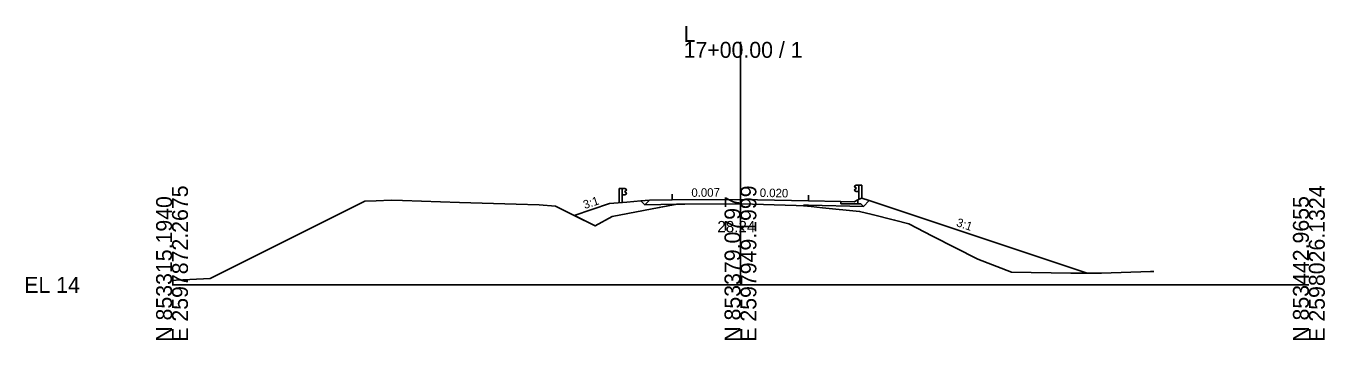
# Model space of a CAD drawing. Extents: x -26 to 1203, y -10 to 9526.
# Drawn here: x -25.7 to 202.8, y 6990.3 to 7045.5 of the extents above; entities that cross this region are included whole.
import ezdxf

# ---------------------------------------------------------------- set-up
doc = ezdxf.new("R2010")
doc.units = 0
for name, color, linetype in [('Exist Cross Section Cell', 7, 'Continuous'), ('Exist XS Center Line Elevation Label', 7, 'Continuous'), ('Exist XS Ground Line', 7, 'Continuous'), ('Prop XS Earthwork Shape', 7, 'Continuous'), ('Prop XS EOT Tick Mark', 7, 'Continuous'), ('Prop XS Finish Grade', 7, 'Continuous'), ('Prop XS Finish Grade Earthwork', 7, 'Continuous'), ('Prop XS Finish Grade Paved Shoulder', 7, 'Continuous'), ('Prop XS Finish Grade Pavement', 7, 'Continuous'), ('Prop XS Guardrail', 7, 'Continuous'), ('Prop XS Pvmt Edge Slope', 7, 'Continuous'), ('Prop XS SBG', 7, 'Continuous'), ('Prop XS SE Text', 7, 'Continuous'), ('Prop XS Side Slope Text', 7, 'Continuous'), ('Prop XS Subgrade Earthwork', 7, 'Continuous')]:
    doc.layers.add(name, color=color, linetype=linetype)

msp = doc.modelspace()

# ---------------------------------------------------------------- linework, layer by layer
at = {"layer": 'Exist Cross Section Cell'}
for p, q in [((100, 7000), (100, 7042.73)), ((0, 7000), (100, 7000)), ((100, 7000), (200, 7000))]:
    msp.add_line(p, q, dxfattribs=at)
at = {"layer": 'Exist XS Ground Line'}
for p, q in [((6.7, 7001.12), (32.07, 7013.81)), ((32.07, 7013.81), (33.91, 7014.73)), ((33.91, 7014.73), (35.91, 7014.79)), ((35.91, 7014.79), (38.54, 7014.87)), ((38.54, 7014.87), (40.54, 7014.81)), ((40.54, 7014.81), (50.55, 7014.51)), ((50.55, 7014.51), (60.56, 7014.21)), ((60.56, 7014.21), (64.57, 7014.09)), ((64.57, 7014.09), (67.48, 7013.86)), ((67.48, 7013.86), (74.43, 7010.38)), ((85.71, 7013.58), (88.86, 7014.2)), ((88.86, 7014.2), (90.2, 7014.21)), ((90.2, 7014.21), (100.2, 7014.24)), ((100.2, 7014.24), (109.81, 7013.95)), ((109.81, 7013.95), (111.12, 7013.93)), ((111.12, 7013.93), (112.45, 7013.77)), ((112.45, 7013.77), (114.46, 7013.56)), ((74.43, 7010.38), (77.41, 7012.04)), ((77.41, 7012.04), (85.71, 7013.58)), ((114.46, 7013.56), (120.95, 7012.91)), ((120.95, 7012.91), (123.15, 7012.36)), ((123.15, 7012.36), (127.11, 7011.4)), ((127.11, 7011.4), (129.61, 7010.71)), ((129.61, 7010.71), (133.78, 7008.54)), ((133.78, 7008.54), (141.75, 7004.52)), ((141.75, 7004.52), (147.66, 7002.22)), ((163.52, 7002.04), (172.11, 7002.36)), ((172.11, 7002.36), (172.71, 7002.38)), ((0, 7000.77), (0.74, 7000.81)), ((0.74, 7000.81), (6.7, 7001.12)), ((147.66, 7002.22), (158.11, 7002.04)), ((158.11, 7002.04), (163.52, 7002.04))]:
    msp.add_line(p, q, dxfattribs=at)
at = {"layer": 'Prop XS Earthwork Shape'}
for points in [[(88.74, 7014.18), (83.19, 7014.07), (82.5, 7014.76), (80, 7014.56), (76.99, 7014.32), (70.73, 7012.23), (74.43, 7010.38), (77.41, 7012.04), (85.71, 7013.58)], [(88.86, 7014.2), (88.86, 7014.18), (88.74, 7014.18)], [(111.12, 7014.02), (111.12, 7013.93), (112.45, 7013.77), (114.46, 7013.56), (120.95, 7012.91), (123.15, 7012.36), (127.11, 7011.4), (129.61, 7010.71), (133.78, 7008.54), (141.75, 7004.52), (147.66, 7002.22), (158.11, 7002.04), (161.01, 7002.04), (122.64, 7014.83), (121.62, 7013.81), (112, 7014)]]:
    msp.add_lwpolyline(points, close=True, dxfattribs=at)
at = {"layer": 'Prop XS EOT Tick Mark'}
for p, q in [((88, 7014.96), (88, 7015.96)), ((112, 7014.79), (112, 7015.79))]:
    msp.add_line(p, q, dxfattribs=at)
at = {"layer": 'Prop XS Finish Grade'}
for p, q in [((84, 7014.88), (82.5, 7014.76)), ((120.67, 7014.93), (121.31, 7015.25)), ((121.33, 7015.26), (122.64, 7014.83))]:
    msp.add_line(p, q, dxfattribs=at)
at = {"layer": 'Prop XS Finish Grade Earthwork'}
for p, q in [((76.99, 7014.32), (70.73, 7012.23)), ((80, 7014.56), (76.99, 7014.32)), ((82.5, 7014.76), (80, 7014.56)), ((122.64, 7014.83), (161.01, 7002.04))]:
    msp.add_line(p, q, dxfattribs=at)
at = {"layer": 'Prop XS Finish Grade Paved Shoulder'}
for p, q in [((88, 7014.96), (84, 7014.88)), ((112, 7014.79), (117.67, 7014.68))]:
    msp.add_line(p, q, dxfattribs=at)
at = {"layer": 'Prop XS Finish Grade Pavement'}
for p, q in [((88, 7014.96), (100, 7015.03)), ((100, 7015.03), (112, 7014.79))]:
    msp.add_line(p, q, dxfattribs=at)
at = {"layer": 'Prop XS Guardrail'}
for p, q in [((78.67, 7016.95), (79.17, 7016.95)), ((78.67, 7014.45), (78.67, 7016.95)), ((79.17, 7016.95), (79.67, 7016.95)), ((79.17, 7016.95), (79.17, 7014.45)), ((79.67, 7016.95), (79.96, 7016.75)), ((79.96, 7016.63), (79.67, 7016.43)), ((79.67, 7016.43), (79.67, 7016.34)), ((79.67, 7016.34), (79.96, 7016.14)), ((79.96, 7016.02), (79.67, 7015.82)), ((79.96, 7016.75), (79.99, 7016.69)), ((79.99, 7016.69), (79.96, 7016.63)), ((79.96, 7016.14), (79.99, 7016.08)), ((79.99, 7016.08), (79.96, 7016.02)), ((120.04, 7017.36), (120.01, 7017.3)), ((120.01, 7017.3), (120.04, 7017.24)), ((120.04, 7016.74), (120.01, 7016.68)), ((120.01, 7016.68), (120.04, 7016.62)), ((120.33, 7017.56), (120.04, 7017.36)), ((120.04, 7017.24), (120.33, 7017.04)), ((120.33, 7016.94), (120.04, 7016.74)), ((120.04, 7016.62), (120.33, 7016.42)), ((120.83, 7017.56), (120.33, 7017.56)), ((120.33, 7017.04), (120.33, 7016.94)), ((120.33, 7016.42), (120.83, 7016.42)), ((121.33, 7017.56), (120.83, 7017.56)), ((120.83, 7017.56), (120.83, 7015.01)), ((121.33, 7015.26), (121.33, 7017.56)), ((79.67, 7015.82), (79.17, 7015.82))]:
    msp.add_line(p, q, dxfattribs=at)
at = {"layer": 'Prop XS Pvmt Edge Slope'}
for p, q in [((84, 7014.88), (83.19, 7014.07)), ((120.67, 7014.26), (121.17, 7014.26)), ((121.17, 7014.26), (121.62, 7013.81))]:
    msp.add_line(p, q, dxfattribs=at)
at = {"layer": 'Prop XS SBG'}
for p, q in [((117.67, 7014.68), (117.67, 7014.26)), ((120, 7014.6), (117.67, 7014.68)), ((117.67, 7014.26), (120.67, 7014.26)), ((120.67, 7014.93), (120, 7014.6)), ((120.67, 7014.26), (120.67, 7014.93))]:
    msp.add_line(p, q, dxfattribs=at)
at = {"layer": 'Prop XS Subgrade Earthwork'}
for p, q in [((83.19, 7014.07), (82.5, 7014.76)), ((88.86, 7014.18), (83.19, 7014.07)), ((88.86, 7014.2), (88.86, 7014.18)), ((111.12, 7014.02), (111.12, 7013.93)), ((111.12, 7014.02), (112, 7014)), ((112, 7014), (121.62, 7013.81)), ((121.62, 7013.81), (122.64, 7014.83))]:
    msp.add_line(p, q, dxfattribs=at)

# ---------------------------------------------------------------- texts
at = {"layer": 'Exist Cross Section Cell'}
for s, p in [('L', (90, 7042.73)), ('17+00.00 / 1', (90, 7039.93)), ('EL 14', (-26, 6998.6))]:
    msp.add_text(s, height=2.8, dxfattribs=at).set_placement(p)
for s, p in [('E 2597872.2675', (2.8, 6990)), ('E 2597949.1999', (102.8, 6990)), ('E 2598026.1324', (202.8, 6990)), ('N 853315.1940', (0, 6990)), ('N 853379.0797', (100, 6990)), ('N 853442.9655', (200, 6990))]:
    msp.add_text(s, height=2.8, rotation=90, dxfattribs=at).set_placement(p)
at = {"layer": 'Exist XS Center Line Elevation Label'}
msp.add_text('28.24', height=2, dxfattribs=at).set_placement((95.93, 7009.24))
at = {"layer": 'Prop XS SE Text'}
for s, rotation, p in [('0.007', 0.3745, (91.37, 7015.48)), ('0.020', 358.8542, (103.38, 7015.47))]:
    msp.add_text(s, height=1.5, rotation=rotation, dxfattribs=at).set_placement(p)
at = {"layer": 'Prop XS Side Slope Text'}
for rotation, p in [(18.4349, (72.61, 7013.32)), (341.5651, (137.86, 7010.36))]:
    msp.add_text('3:1', height=1.5, rotation=rotation, dxfattribs=at).set_placement(p)

doc.saveas('drawing.dxf')
